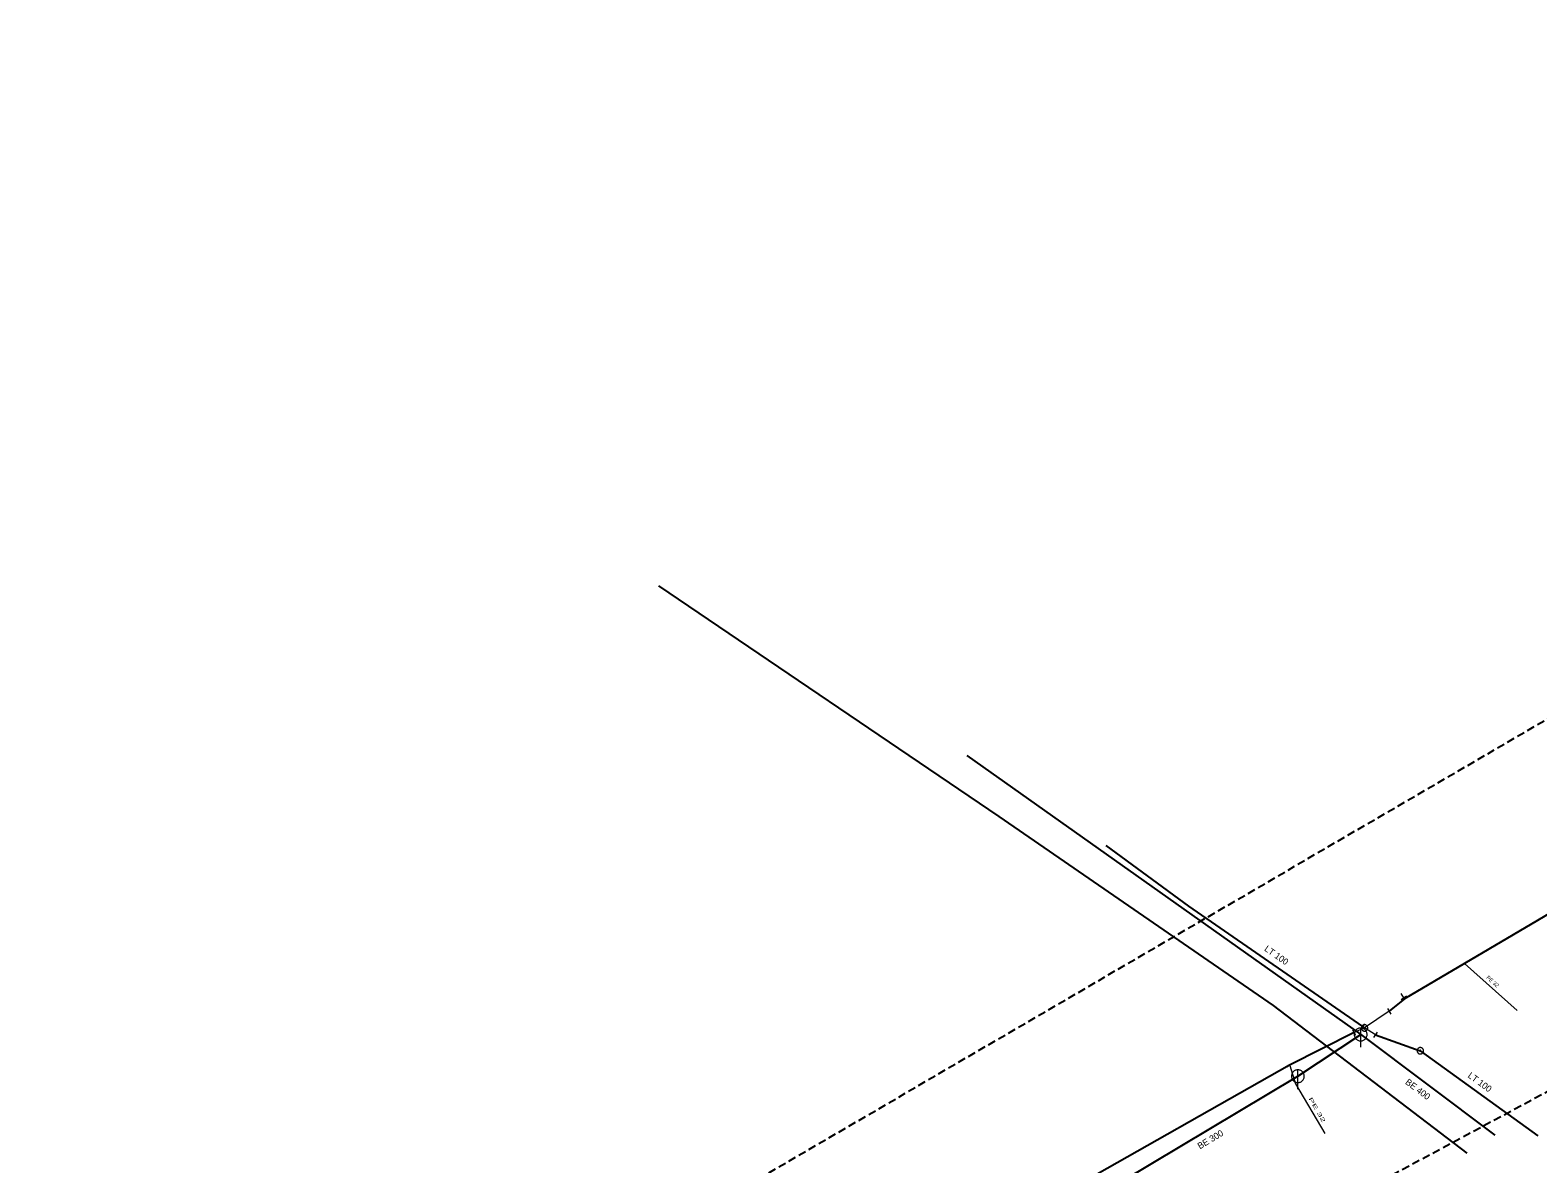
# Model space of a CAD drawing. Extents: x -689189 to -688666, y -973229 to -972850.
# Drawn here: x -689187.5 to -688952.7, y -973062.7 to -972886.1 of the extents above; entities that cross this region are included whole.
import ezdxf

# ---------------------------------------------------------------- set-up
doc = ezdxf.new("R2010")
doc.units = 0
doc.header["$LTSCALE"] = 0.4
doc.linetypes.add('MEDIUM_DASHED', pattern=[4.5, 3, -1.5])
doc.layers.add('1', color=7, linetype='Continuous')
for name, color, linetype, lineweight in [('13', 7, 'Continuous', 13), ('14', 7, 'Continuous', 13), ('17', 7, 'Continuous', 25), ('22', 7, 'Continuous', 13), ('34', 7, 'Continuous', 13), ('47', 7, 'Continuous', 13), ('63', 7, 'MEDIUM_DASHED', 25)]:
    doc.layers.add(name, color=color, linetype=linetype, lineweight=lineweight)

msp = doc.modelspace()

# ---------------------------------------------------------------- linework, layer by layer
at = {"layer": '13'}
for p, q in [((-688964.11, -973031.504), (-688955.864, -973038.815)), ((-688973.55, -973036.829), (-688973.949, -973036.14))]:
    msp.add_line(p, q, dxfattribs=at)
msp.add_lwpolyline([(-688991.317, -973047.392), (-688990.39, -973050.22), (-688985.839, -973057.999)], dxfattribs=at)
at = {"layer": '14', "lineweight": 25}
msp.add_line((-689041.629, -972999.11), (-688980.26, -973042.539), dxfattribs=at)
at = {"layer": '14'}
for p, q in [((-688973.449, -973037.003), (-688973.55, -973036.829)), ((-688975.824, -973038.94), (-688979.659, -973041.533)), ((-688979.912, -973041.327), (-688979.659, -973041.533)), ((-688991.359, -973047.32), (-688991.317, -973047.392))]:
    msp.add_line(p, q, dxfattribs=at)
at = {"layer": '14', "lineweight": 25}
msp.add_lwpolyline([(-689017.43, -973065.379), (-688990.039, -973049.05), (-688980.26, -973042.539), (-688959.374, -973058.21)], dxfattribs=at)
at = {"layer": '14'}
msp.add_lwpolyline([(-688977.96, -973042.606), (-688979.659, -973041.533), (-688981.288, -973042.24)], dxfattribs=at)
at = {"layer": '17'}
for p, q in [((-688977.96, -973042.606), (-688970.972, -973045.085)), ((-688970.972, -973045.085), (-688952.664, -973058.326))]:
    msp.add_line(p, q, dxfattribs=at)
for points in [[(-688793.177, -972931.292), (-688807.995, -972940.316), (-688831.953, -972953.798), (-688872.059, -972977.27), (-688873.897, -972978.38), (-688874.46, -972978.719), (-688897.906, -972992.515), (-688964.11, -973031.504), (-688973.449, -973037.003), (-688975.824, -973038.94)], [(-689089.648, -972972.664), (-689036.627, -973008.611), (-688993.874, -973038.012), (-688963.722, -973061.021)], [(-688979.912, -973041.327), (-689007.01, -973022.548), (-689019.901, -973013.12)], [(-688981.288, -973042.24), (-688991.359, -973047.32), (-689025.954, -973066.95), (-689093.62, -973108.102), (-689137.019, -973132.93)]]:
    msp.add_lwpolyline(points, dxfattribs=at)
at = {"layer": '22'}
for p, q in [((-688980.26, -973044.54), (-688980.259, -973041.54)), ((-688990.04, -973051.05), (-688990.039, -973048.05))]:
    msp.add_line(p, q, dxfattribs=at)
for points in [[(-688979.26, -973042.54), (-688979.265, -973042.431), (-688979.283, -973042.323), (-688979.313, -973042.217), (-688979.353, -973042.116), (-688979.405, -973042.019), (-688979.467, -973041.929), (-688979.539, -973041.846), (-688979.619, -973041.772), (-688979.707, -973041.706), (-688979.801, -973041.651), (-688979.901, -973041.606), (-688980.006, -973041.573), (-688980.113, -973041.551), (-688980.222, -973041.541), (-688980.332, -973041.543), (-688980.44, -973041.557), (-688980.547, -973041.582), (-688980.65, -973041.619), (-688980.748, -973041.668), (-688980.84, -973041.726), (-688980.926, -973041.795), (-688981.003, -973041.872), (-688981.072, -973041.958), (-688981.131, -973042.05), (-688981.179, -973042.148), (-688981.216, -973042.251), (-688981.242, -973042.358), (-688981.256, -973042.466), (-688981.259, -973042.576), (-688981.249, -973042.685), (-688981.228, -973042.792), (-688981.194, -973042.896), (-688981.15, -973042.996), (-688981.095, -973043.091), (-688981.029, -973043.179), (-688980.955, -973043.259), (-688980.872, -973043.331), (-688980.782, -973043.393), (-688980.686, -973043.445), (-688980.584, -973043.486), (-688980.479, -973043.516), (-688980.371, -973043.534), (-688980.261, -973043.54), (-688980.152, -973043.534), (-688980.044, -973043.516), (-688979.939, -973043.487), (-688979.837, -973043.446), (-688979.74, -973043.394), (-688979.65, -973043.332), (-688979.567, -973043.261), (-688979.492, -973043.181), (-688979.427, -973043.093), (-688979.371, -973042.999), (-688979.327, -973042.899), (-688979.293, -973042.795), (-688979.271, -973042.687), (-688979.261, -973042.578)], [(-688989.04, -973049.05), (-688989.045, -973048.941), (-688989.063, -973048.833), (-688989.093, -973048.727), (-688989.133, -973048.626), (-688989.185, -973048.529), (-688989.247, -973048.439), (-688989.319, -973048.356), (-688989.399, -973048.282), (-688989.487, -973048.216), (-688989.581, -973048.161), (-688989.681, -973048.116), (-688989.786, -973048.083), (-688989.893, -973048.061), (-688990.002, -973048.051), (-688990.112, -973048.053), (-688990.22, -973048.067), (-688990.327, -973048.092), (-688990.43, -973048.129), (-688990.528, -973048.178), (-688990.62, -973048.236), (-688990.706, -973048.305), (-688990.783, -973048.382), (-688990.852, -973048.468), (-688990.911, -973048.56), (-688990.959, -973048.658), (-688990.996, -973048.761), (-688991.022, -973048.868), (-688991.036, -973048.976), (-688991.039, -973049.086), (-688991.029, -973049.195), (-688991.008, -973049.302), (-688990.974, -973049.406), (-688990.93, -973049.506), (-688990.875, -973049.601), (-688990.809, -973049.689), (-688990.735, -973049.769), (-688990.652, -973049.841), (-688990.562, -973049.903), (-688990.466, -973049.955), (-688990.364, -973049.996), (-688990.259, -973050.026), (-688990.151, -973050.044), (-688990.041, -973050.05), (-688989.932, -973050.044), (-688989.824, -973050.026), (-688989.719, -973049.997), (-688989.617, -973049.956), (-688989.52, -973049.904), (-688989.43, -973049.842), (-688989.347, -973049.771), (-688989.272, -973049.691), (-688989.207, -973049.603), (-688989.151, -973049.509), (-688989.107, -973049.409), (-688989.073, -973049.305), (-688989.051, -973049.197), (-688989.041, -973049.088)]]:
    msp.add_lwpolyline(points, close=True, dxfattribs=at)
at = {"layer": '34'}
for p, q in [((-688973.965, -973037.107), (-688973.134, -973036.551)), ((-688976.075, -973038.507), (-688975.573, -973039.372)), ((-688981.535, -973041.805), (-688981.04, -973042.674)), ((-688979.638, -973040.908), (-688980.186, -973041.744)), ((-688977.676, -973042.193), (-688978.244, -973043.017)), ((-688990.887, -973047.136), (-688991.747, -973047.646))]:
    msp.add_line(p, q, dxfattribs=at)
at = {"layer": '47'}
for points in [[(-688979.238, -973041.804), (-688979.213, -973041.758), (-688979.191, -973041.71), (-688979.176, -973041.661), (-688979.164, -973041.61), (-688979.159, -973041.557), (-688979.16, -973041.505), (-688979.166, -973041.453), (-688979.177, -973041.402), (-688979.192, -973041.353), (-688979.214, -973041.304), (-688979.24, -973041.259), (-688979.272, -973041.217), (-688979.306, -973041.178), (-688979.345, -973041.143), (-688979.387, -973041.112), (-688979.433, -973041.087), (-688979.481, -973041.065), (-688979.531, -973041.049), (-688979.581, -973041.038), (-688979.634, -973041.033), (-688979.686, -973041.034), (-688979.739, -973041.039), (-688979.79, -973041.05), (-688979.839, -973041.066), (-688979.887, -973041.088), (-688979.932, -973041.114), (-688979.975, -973041.145), (-688980.013, -973041.18), (-688980.048, -973041.219), (-688980.079, -973041.261), (-688980.104, -973041.307), (-688980.126, -973041.355), (-688980.142, -973041.405), (-688980.153, -973041.455), (-688980.158, -973041.508), (-688980.158, -973041.56), (-688980.153, -973041.612), (-688980.142, -973041.663), (-688980.125, -973041.713), (-688980.103, -973041.761), (-688980.077, -973041.806), (-688980.047, -973041.848), (-688980.011, -973041.887), (-688979.972, -973041.922), (-688979.93, -973041.953), (-688979.884, -973041.978), (-688979.836, -973042), (-688979.787, -973042.016), (-688979.736, -973042.027), (-688979.683, -973042.032), (-688979.631, -973042.032), (-688979.58, -973042.026), (-688979.528, -973042.015), (-688979.479, -973041.999), (-688979.43, -973041.977), (-688979.385, -973041.951), (-688979.343, -973041.92), (-688979.304, -973041.885), (-688979.269, -973041.846)], [(-688979.59, -973041.577), (-688979.585, -973041.569), (-688979.582, -973041.562), (-688979.579, -973041.554), (-688979.578, -973041.545), (-688979.577, -973041.537), (-688979.577, -973041.528), (-688979.577, -973041.519), (-688979.579, -973041.511), (-688979.582, -973041.503), (-688979.586, -973041.495), (-688979.59, -973041.487), (-688979.595, -973041.481), (-688979.601, -973041.475), (-688979.606, -973041.468), (-688979.614, -973041.464), (-688979.622, -973041.459), (-688979.629, -973041.456), (-688979.637, -973041.453), (-688979.646, -973041.452), (-688979.654, -973041.451), (-688979.663, -973041.451), (-688979.672, -973041.451), (-688979.68, -973041.453), (-688979.689, -973041.456), (-688979.696, -973041.46), (-688979.704, -973041.464), (-688979.71, -973041.469), (-688979.716, -973041.475), (-688979.723, -973041.48), (-688979.727, -973041.488), (-688979.732, -973041.496), (-688979.735, -973041.503), (-688979.738, -973041.511), (-688979.739, -973041.52), (-688979.74, -973041.528), (-688979.741, -973041.536), (-688979.74, -973041.546), (-688979.738, -973041.554), (-688979.735, -973041.563), (-688979.731, -973041.57), (-688979.727, -973041.578), (-688979.722, -973041.584), (-688979.716, -973041.59), (-688979.711, -973041.597), (-688979.703, -973041.601), (-688979.695, -973041.606), (-688979.688, -973041.609), (-688979.68, -973041.612), (-688979.671, -973041.613), (-688979.663, -973041.614), (-688979.655, -973041.615), (-688979.645, -973041.614), (-688979.637, -973041.612), (-688979.629, -973041.609), (-688979.621, -973041.605), (-688979.613, -973041.601), (-688979.607, -973041.596), (-688979.601, -973041.59), (-688979.594, -973041.585)], [(-688970.472, -973045.085), (-688970.475, -973045.032), (-688970.483, -973044.98), (-688970.497, -973044.931), (-688970.514, -973044.882), (-688970.539, -973044.835), (-688970.568, -973044.791), (-688970.6, -973044.75), (-688970.637, -973044.713), (-688970.678, -973044.681), (-688970.722, -973044.652), (-688970.769, -973044.627), (-688970.818, -973044.61), (-688970.867, -973044.596), (-688970.919, -973044.588), (-688970.972, -973044.585), (-688971.024, -973044.588), (-688971.076, -973044.596), (-688971.127, -973044.61), (-688971.174, -973044.627), (-688971.222, -973044.652), (-688971.266, -973044.681), (-688971.306, -973044.713), (-688971.343, -973044.75), (-688971.377, -973044.791), (-688971.404, -973044.835), (-688971.429, -973044.882), (-688971.448, -973044.931), (-688971.46, -973044.98), (-688971.468, -973045.032), (-688971.472, -973045.085), (-688971.468, -973045.137), (-688971.46, -973045.189), (-688971.448, -973045.24), (-688971.429, -973045.288), (-688971.404, -973045.335), (-688971.377, -973045.379), (-688971.343, -973045.419), (-688971.306, -973045.456), (-688971.266, -973045.49), (-688971.222, -973045.517), (-688971.174, -973045.542), (-688971.127, -973045.561), (-688971.076, -973045.573), (-688971.024, -973045.581), (-688970.972, -973045.585), (-688970.919, -973045.581), (-688970.867, -973045.573), (-688970.818, -973045.561), (-688970.769, -973045.542), (-688970.722, -973045.517), (-688970.678, -973045.49), (-688970.637, -973045.456), (-688970.6, -973045.419), (-688970.568, -973045.379), (-688970.539, -973045.335), (-688970.514, -973045.288), (-688970.497, -973045.24), (-688970.483, -973045.189), (-688970.475, -973045.137)], [(-688970.889, -973045.085), (-688970.889, -973045.076), (-688970.892, -973045.068), (-688970.894, -973045.059), (-688970.897, -973045.051), (-688970.901, -973045.044), (-688970.906, -973045.037), (-688970.911, -973045.029), (-688970.916, -973045.024), (-688970.924, -973045.019), (-688970.931, -973045.014), (-688970.938, -973045.01), (-688970.946, -973045.007), (-688970.955, -973045.005), (-688970.963, -973045.002), (-688970.972, -973045.002), (-688970.98, -973045.002), (-688970.989, -973045.005), (-688970.997, -973045.007), (-688971.005, -973045.01), (-688971.012, -973045.014), (-688971.019, -973045.019), (-688971.027, -973045.024), (-688971.032, -973045.029), (-688971.039, -973045.037), (-688971.043, -973045.044), (-688971.046, -973045.051), (-688971.049, -973045.059), (-688971.051, -973045.068), (-688971.054, -973045.076), (-688971.054, -973045.085), (-688971.054, -973045.093), (-688971.051, -973045.102), (-688971.049, -973045.11), (-688971.046, -973045.118), (-688971.043, -973045.125), (-688971.039, -973045.132), (-688971.032, -973045.14), (-688971.027, -973045.146), (-688971.019, -973045.152), (-688971.012, -973045.156), (-688971.005, -973045.159), (-688970.997, -973045.163), (-688970.989, -973045.164), (-688970.98, -973045.167), (-688970.972, -973045.167), (-688970.963, -973045.167), (-688970.955, -973045.164), (-688970.946, -973045.163), (-688970.938, -973045.159), (-688970.931, -973045.156), (-688970.924, -973045.152), (-688970.916, -973045.146), (-688970.911, -973045.14), (-688970.906, -973045.132), (-688970.901, -973045.125), (-688970.897, -973045.118), (-688970.894, -973045.11), (-688970.892, -973045.102), (-688970.889, -973045.093)]]:
    msp.add_lwpolyline(points, close=True, dxfattribs=at)
at = {"layer": '63'}
msp.add_lwpolyline([(-689164.065, -973177.51), (-689187.511, -973131.176), (-688767.155, -972886.107), (-688767.155, -972886.107), (-688777.761, -972958.121), (-688777.761, -972958.121), (-688989.335, -973072.002), (-688989.335, -973072.002)], close=True, dxfattribs=at)

# ---------------------------------------------------------------- texts
at = {"layer": '1'}
for s, height, rotation, p in [('LT 100', 1, 325, (-688995.365, -973029.419)), ('PE 32 ', 0.6, 318, (-688960.75, -973033.759)), ('BE 400', 1, 323, (-688973.407, -973050.162)), ('LT 100', 1, 324, (-688963.671, -973049.149)), ('BE 300', 1, 31, (-689005.294, -973060.455))]:
    msp.add_text(s, height=height, rotation=rotation, dxfattribs=at).set_placement(p)
at = {"layer": '1', "width": 2}
msp.add_text('PE 32 ', height=0.6, rotation=300, dxfattribs=at).set_placement((-688988.404, -973052.54))

doc.saveas('drawing.dxf')
